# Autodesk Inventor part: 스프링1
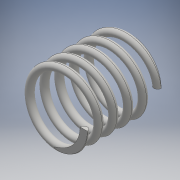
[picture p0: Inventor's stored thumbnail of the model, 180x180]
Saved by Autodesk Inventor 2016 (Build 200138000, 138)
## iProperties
Created: 2019-11
Part Number: 스프링1
Material: 일반
Document SubType Name: Modeling
Designer: user
Density: 1 g/cm^3
Appearance: 기본값
Mass: 0.822006 g
Surface Area: 16.7268 cm^2
Volume: 0.822006 cm^3
Author: user
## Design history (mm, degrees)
sketch "스케치1"
  geometry: L1 (0, 0)-(8.5, 0); L2 (8.5, 0)-(8.5, 20.5); L3 (8.5, 20.5)-(0, 20.5); L4 (0, 20.5)-(0, 0); C1 r 1 at (8.5, 0)
  constraints: 8 end point, 2 parallel, 1 centre point, 1 coincident, 1 horizontal, 1 perpendicular
  dimensions: "d0" = 17 diameter of L2 L4; "d1" = 2 diameter of C1; "d2" = 20.5 distance of L1.end L2.end (derived)
feature "코일1" sketch "스케치1" pitch "d3" = 10; turns "d5" = 5; dims "d4" = 20.5 (= d2), "d6" = 0, angle "d7" = 90 deg, angle "d8" = 90 deg, "d9" = 0, "d10" = 0
sketch "스케치2"
  geometry: L1 (-15.597, 20.5)-(15.597, 20.5); L2 (15.597, 20.5)-(15.597, 0); L3 (15.597, 0)-(-15.597, 0); L4 (-15.597, 0)-(-15.597, 20.5); 2 further points
  constraints: 8 end point, 2 parallel, 1 coincident, 1 horizontal, 1 midpoint, 1 perpendicular
  dimensions: "d11" = 20.5 distance of L1.end L2.end (= d2)
extrude "돌출1" sketch "스케치2" stored distance "d12" = 50; taper "d13" = 0 deg
node "솔리드1"
